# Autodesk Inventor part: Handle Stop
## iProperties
Shininess: 77.0
Length Units: 11269
Angle Units: 11279
Time Units: 11290
Mass Units: 11283
Length Display Precision: 3
Angle Display Precision: 2
Compacted: True
Created: 2002-02
Part Number: Handle Stop
Document SubType Name: Modeling
Designer: ***
Density: 0.0
Volumn: 0.0
Area: 0.0
PropertySet Name: Model Information
Control State: 0
Master: False
Checked Out: False
Author: ***
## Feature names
1. Revolution1
